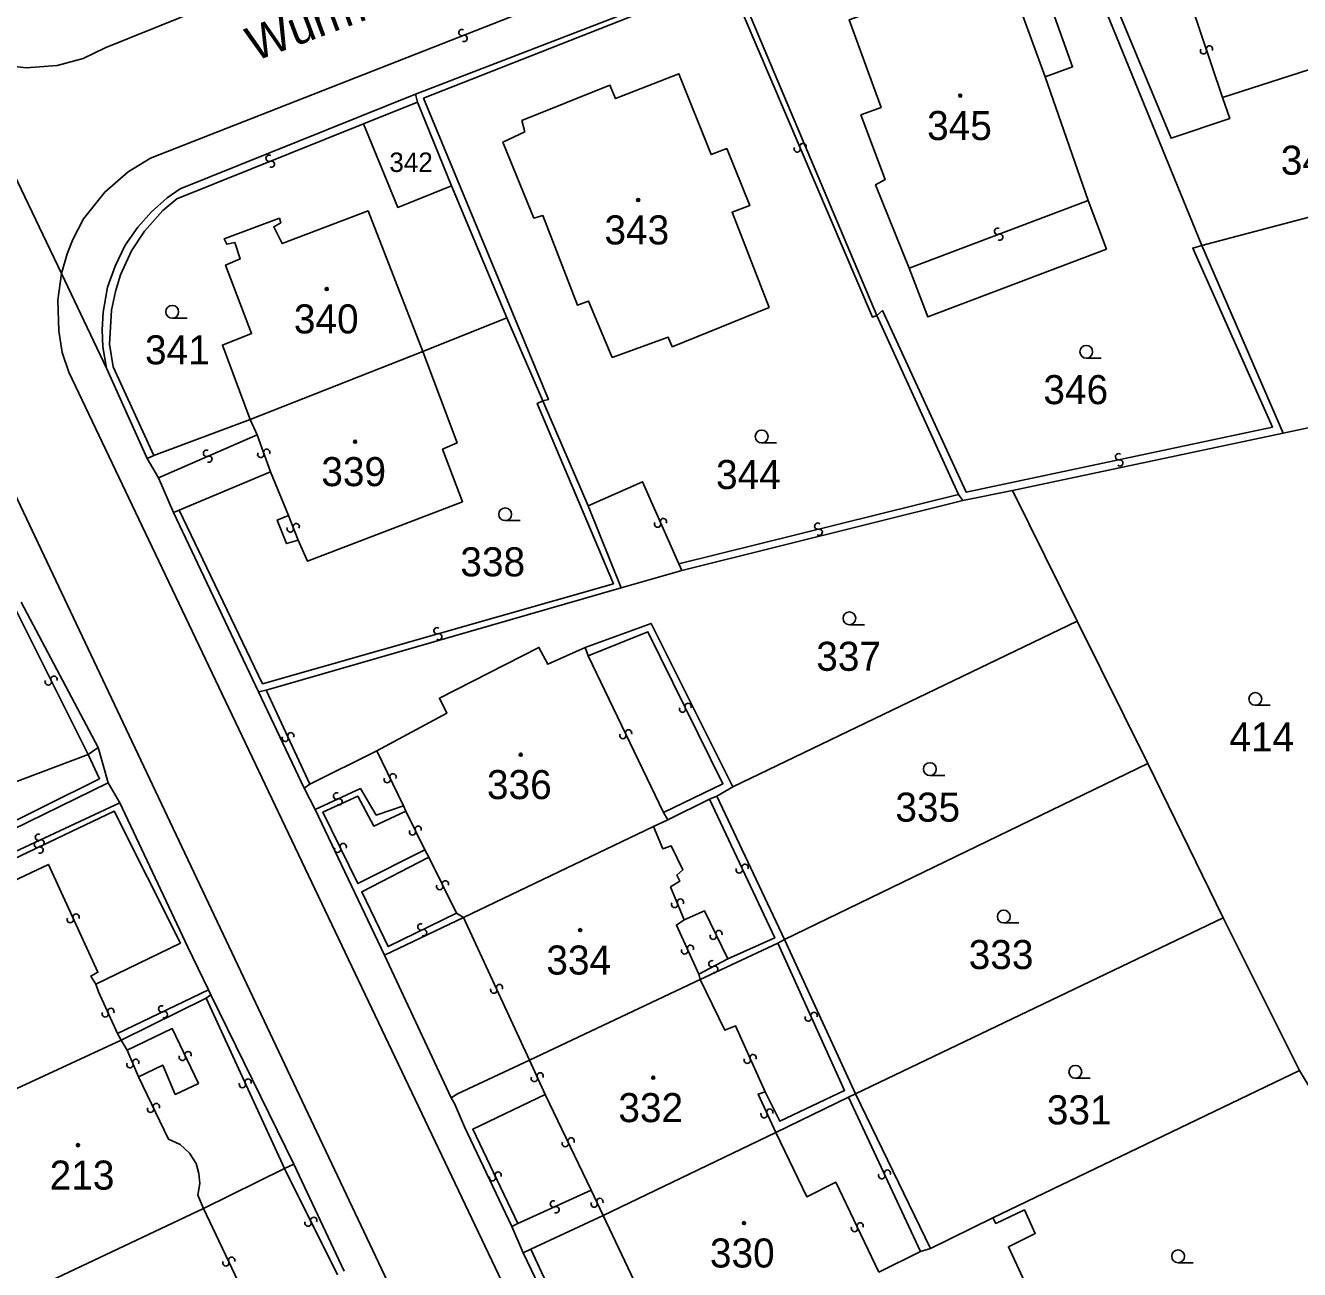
# Model space of a CAD drawing. Extents: x -600391 to -599491, y -1160176 to -1159402.
# Drawn here: x -600227.7 to -600153, y -1159733.9 to -1159661.1 of the extents above; entities that cross this region are included whole.
import ezdxf

# ---------------------------------------------------------------- set-up
doc = ezdxf.new("R2010")
doc.units = 0
for name, color, linetype in [('Level 1', 7, 'Continuous'), ('Level 11', 7, 'Continuous'), ('Level 13', 7, 'Continuous'), ('Level 3', 7, 'Continuous'), ('Level 4', 7, 'Continuous'), ('Level 5', 7, 'Continuous')]:
    doc.layers.add(name, color=color, linetype=linetype)

msp = doc.modelspace()

# ---------------------------------------------------------------- linework, layer by layer
at = {"layer": 'Level 1'}
for points in [[(-600170.28, -1159652.49), (-600166.33, -1159663.53), (-600167.93, -1159664.11)], [(-600160.77, -1159655.83), (-600164.91, -1159657.24), (-600160.56, -1159667.71), (-600157.13, -1159666.55), (-600157.55, -1159665.32)], [(-600165.9, -1159656.5), (-600158.77, -1159673.99)], [(-600204.82, -1159665.14), (-600186.4, -1159658.03)], [(-600175.9, -1159675.31), (-600177.87, -1159670.44), (-600177.31, -1159670.13), (-600178.73, -1159666.35), (-600177.55, -1159665.91), (-600179.41, -1159660.78), (-600170.34, -1159657.54)], [(-600186.15, -1159658.3), (-600177.79, -1159678.09)], [(-600157.55, -1159665.32), (-600151.9, -1159663.52), (-600152.17, -1159662.59), (-600147.93, -1159661.35)], [(-600231.91, -1159662.36), (-600226.43, -1159673.8), (-600225.55, -1159675.64)], [(-600184.1, -1159677.62), (-600189.78, -1159679.92), (-600190.02, -1159679.35), (-600193.29, -1159680.54), (-600194.68, -1159677.25), (-600195.33, -1159677.48), (-600197.36, -1159672.23), (-600197.89, -1159672.39), (-600199.7, -1159667.95), (-600198.41, -1159667.34), (-600198.58, -1159666.67), (-600193.43, -1159664.6), (-600193.09, -1159665.39), (-600189.39, -1159663.94), (-600187.5, -1159668.67), (-600186.58, -1159668.32), (-600185.24, -1159671.66), (-600186.27, -1159672.05), (-600184.1, -1159677.62)], [(-600167.93, -1159664.11), (-600165.41, -1159671.35)], [(-600204.82, -1159665.14), (-600218.6, -1159670.68), (-600219.35, -1159671.21), (-600220.28, -1159672.03), (-600221.08, -1159672.92), (-600221.81, -1159673.97), (-600222.41, -1159675.2), (-600222.85, -1159676.43), (-600223.1, -1159677.89), (-600223.16, -1159678.93), (-600223.12, -1159679.92), (-600222.9, -1159681.18)], [(-600207.85, -1159666.87), (-600204.69, -1159665.61)], [(-600204.82, -1159665.14), (-600204.69, -1159665.61)], [(-600204.69, -1159665.61), (-600202.7, -1159670.5)], [(-600202.7, -1159670.5), (-600205.85, -1159671.76), (-600207.85, -1159666.87)], [(-600202.7, -1159670.5), (-600199.46, -1159678.22)], [(-600144.73, -1159670.29), (-600158.77, -1159673.99)], [(-600165.41, -1159671.35), (-600164.35, -1159674.2), (-600174.81, -1159678.17), (-600175.9, -1159675.31)], [(-600214.49, -1159684.17), (-600216.12, -1159679.82), (-600214.41, -1159679.15), (-600215.93, -1159675.14), (-600215.08, -1159674.78), (-600215.4, -1159673.82), (-600215.87, -1159673.92), (-600216.01, -1159673.6), (-600212.78, -1159672.4), (-600212.69, -1159672.66), (-600213.11, -1159672.89), (-600212.62, -1159673.88), (-600207.59, -1159671.97), (-600204.38, -1159680.19)], [(-600158.77, -1159673.99), (-600153.99, -1159684.97)], [(-600222.9, -1159681.18), (-600225.55, -1159675.64)], [(-600116.25, -1159676.91), (-600153.99, -1159684.97)], [(-600204.38, -1159680.19), (-600199.46, -1159678.22)], [(-600199.46, -1159678.22), (-600197.36, -1159683.08)], [(-600177.79, -1159678.09), (-600173.02, -1159688.57)], [(-600214.49, -1159684.17), (-600204.38, -1159680.19)], [(-600211.68, -1159691.24), (-600211.14, -1159692.48), (-600202.06, -1159688.99), (-600203.23, -1159685.92), (-600202.38, -1159685.54), (-600204.38, -1159680.19)], [(-600220.52, -1159686.47), (-600222.9, -1159681.18)], [(-600197.36, -1159683.08), (-600194.7, -1159689.23)], [(-600220.13, -1159686.28), (-600214.49, -1159684.17)], [(-600153.99, -1159684.97), (-600169.84, -1159688.34)], [(-600220.52, -1159686.47), (-600220.13, -1159686.28)], [(-600219.87, -1159687.59), (-600220.52, -1159686.47)], [(-600218.65, -1159689.49), (-600213.3, -1159687.24)], [(-600213.3, -1159687.24), (-600212.25, -1159689.79)], [(-600218.99, -1159689.62), (-600219.87, -1159687.59)], [(-600173.02, -1159688.57), (-600172.76, -1159688.92)], [(-600172.76, -1159688.92), (-600169.84, -1159688.34)], [(-600169.84, -1159688.34), (-600166.06, -1159695.99)], [(-600218.99, -1159689.62), (-600218.65, -1159689.49)], [(-600194.7, -1159689.23), (-600192.77, -1159694.04)], [(-600189.22, -1159693.02), (-600172.76, -1159688.92)], [(-600214, -1159700.13), (-600218.99, -1159689.62)], [(-600212.25, -1159689.79), (-600212.91, -1159690.07), (-600212.36, -1159691.44), (-600211.68, -1159691.24)], [(-600192.77, -1159694.04), (-600189.22, -1159693.02)], [(-600213.56, -1159700.02), (-600192.77, -1159694.04)], [(-600223.39, -1159703.37), (-600227.91, -1159694.88)], [(-600194.87, -1159697.52), (-600191.02, -1159696.12), (-600186.23, -1159705.69)], [(-600186.23, -1159705.69), (-600166.06, -1159695.99)], [(-600166.06, -1159695.99), (-600161.93, -1159704.32)], [(-600207.07, -1159703.58), (-600202.98, -1159701.37), (-600203.41, -1159700.5), (-600197.58, -1159697.52), (-600197.06, -1159698.51), (-600194.87, -1159697.52)], [(-600214, -1159700.13), (-600213.56, -1159700.02)], [(-600211.33, -1159705.75), (-600214, -1159700.13)], [(-600223.99, -1159703.78), (-600223.39, -1159703.37)], [(-600222.82, -1159705.45), (-600223.39, -1159703.37)], [(-600211.01, -1159705.53), (-600207.07, -1159703.58)], [(-600244.9, -1159711.81), (-600241.06, -1159710.22), (-600223.99, -1159703.78)], [(-600183.2, -1159714.62), (-600161.93, -1159704.32)], [(-600161.93, -1159704.32), (-600157.51, -1159713.35)], [(-600222.13, -1159706.61), (-600222.82, -1159705.45)], [(-600211.33, -1159705.75), (-600211.01, -1159705.53)], [(-600210.69, -1159707), (-600211.33, -1159705.75)], [(-600187.16, -1159706.22), (-600186.23, -1159705.69)], [(-600216.94, -1159717.57), (-600218.15, -1159715.06), (-600222.13, -1159706.61)], [(-600190.03, -1159707.61), (-600187.59, -1159706.4)], [(-600187.59, -1159706.4), (-600187.16, -1159706.22)], [(-600187.16, -1159706.22), (-600183.2, -1159714.62)], [(-600206.62, -1159715.54), (-600210.69, -1159707)], [(-600202, -1159713.34), (-600190.88, -1159708.01)], [(-600190.88, -1159708.01), (-600190.03, -1159707.61)], [(-600206.62, -1159715.54), (-600202, -1159713.34)], [(-600179.05, -1159723.65), (-600157.51, -1159713.35)], [(-600157.51, -1159713.35), (-600153.05, -1159722.28)], [(-600188.15, -1159716.96), (-600183.6, -1159714.83)], [(-600183.6, -1159714.83), (-600183.2, -1159714.62)], [(-600183.2, -1159714.62), (-600179.05, -1159723.65)], [(-600202.72, -1159723.89), (-600206.62, -1159715.54)], [(-600198.13, -1159721.68), (-600188.15, -1159716.96)], [(-600217.08, -1159718.06), (-600216.79, -1159717.85)], [(-600216.79, -1159717.85), (-600216.94, -1159717.57)], [(-600211.94, -1159727.78), (-600216.79, -1159717.85)], [(-600222.05, -1159720.52), (-600217.08, -1159718.06)], [(-600232.68, -1159725.43), (-600222.05, -1159720.52)], [(-600202.72, -1159723.89), (-600202.36, -1159723.65), (-600198.13, -1159721.68)], [(-600171.01, -1159730.92), (-600153.05, -1159722.28)], [(-600153.05, -1159722.28), (-600152.3, -1159723.51)], [(-600179.45, -1159723.85), (-600179.05, -1159723.65)], [(-600179.05, -1159723.65), (-600174.65, -1159732.7)], [(-600199.18, -1159731.41), (-600201.95, -1159725.58), (-600202.52, -1159724.21), (-600202.72, -1159723.89)], [(-600183.7, -1159725.92), (-600179.45, -1159723.85)], [(-600193.83, -1159730.77), (-600183.7, -1159725.92)], [(-600217.22, -1159730.36), (-600212.49, -1159728.03)], [(-600212.49, -1159728.03), (-600211.94, -1159727.78)], [(-600208.99, -1159734.03), (-600211.94, -1159727.78)], [(-600227.96, -1159735.44), (-600217.22, -1159730.36)], [(-600171.01, -1159730.92), (-600170.82, -1159731.24), (-600169.15, -1159730.44), (-600168.52, -1159731.82), (-600170.09, -1159732.6), (-600166.61, -1159740.12), (-600171.26, -1159742.42)], [(-600198.05, -1159732.74), (-600193.83, -1159730.77)], [(-600174.65, -1159732.7), (-600171.01, -1159730.92)], [(-600198.5, -1159732.97), (-600199.18, -1159731.41)], [(-600198.5, -1159732.97), (-600198.05, -1159732.74)], [(-600175.23, -1159732.89), (-600174.65, -1159732.7)], [(-600195.05, -1159740.16), (-600198.5, -1159732.97)], [(-600177.67, -1159734.1), (-600175.23, -1159732.89)]]:
    msp.add_lwpolyline(points, dxfattribs=at)
at = {"layer": 'Level 13'}
for centre, start, end in [((-600202.096, -1159661.528), 58.58615, 291.17615), ((-600201.964, -1159661.872), 238.8006, 110.8986), ((-600158.665, -1159662.598), 145.87151, 18.46151), ((-600158.315, -1159662.482), 326.08596, 198.18396), ((-600182.46, -1159668.342), 150.31152, 22.90152), ((-600182.12, -1159668.199), 330.52598, 202.62397), ((-600213.387, -1159668.888), 59.23732, 291.33532), ((-600213.252, -1159669.231), 239.02287, 111.61287), ((-600170.724, -1159673.158), 57.83992, 290.42992), ((-600170.596, -1159673.503), 238.05438, 110.15237), ((-600217.052, -1159686.16), 60.92927, 293.02727), ((-600216.907, -1159686.499), 240.71481, 113.30481), ((-600213.874, -1159686.221), 147.37704, 19.47503), ((-600213.527, -1159686.098), 327.16258, 199.75258), ((-600163.637, -1159686.359), 49.36925, 281.46725), ((-600163.563, -1159686.72), 229.15479, 101.74479), ((-600190.629, -1159690.303), 150.84387, 23.43387), ((-600190.29, -1159690.157), 331.05833, 203.15632), ((-600181.253, -1159690.421), 51.29369, 283.39169), ((-600212.142, -1159690.586), 148.83269, 20.93069), ((-600211.798, -1159690.453), 328.61824, 201.20824), ((-600181.167, -1159690.779), 231.07924, 103.66924), ((-600203.549, -1159696.542), 53.28867, 285.38666), ((-600203.45, -1159696.897), 233.07421, 105.66421), ((-600225.984, -1159699.379), 333.91128, 206.00928), ((-600226.315, -1159699.542), 153.69683, 26.28683), ((-600189.175, -1159701.131), 153.41349, 26.00349), ((-600188.844, -1159700.97), 333.62794, 205.72594), ((-600212.448, -1159702.846), 152.20719, 24.30519), ((-600212.113, -1159702.693), 331.99274, 204.58274), ((-600192.666, -1159702.679), 152.86635, 25.45635), ((-600192.333, -1159702.522), 333.08081, 205.1788), ((-600206.134, -1159705.101), 332.9326, 205.5226), ((-600206.467, -1159705.259), 153.14705, 25.24505), ((-600209.436, -1159706.222), 62.09301, 294.191), ((-600209.284, -1159706.558), 241.87855, 114.46855), ((-600204.654, -1159708.16), 333.31626, 205.90626), ((-600226.958, -1159709.053), 62.54886, 295.13886), ((-600226.896, -1159708.632), 62.32947, 294.42747), ((-600226.743, -1159708.967), 242.11501, 114.70501), ((-600204.986, -1159708.32), 153.53072, 25.62871), ((-600226.802, -1159709.387), 242.76332, 114.86132), ((-600209.376, -1159709.34), 153.49748, 25.59548), ((-600209.044, -1159709.18), 333.28303, 205.87303), ((-600185.513, -1159710.392), 332.32545, 204.91545), ((-600185.848, -1159710.547), 152.53991, 24.63791), ((-600203.396, -1159711.52), 153.72714, 25.82514), ((-600203.065, -1159711.359), 333.51268, 206.10268), ((-600189.64, -1159712.57), 149.67266, 22.26266), ((-600189.299, -1159712.431), 329.88712, 201.98512), ((-600225.028, -1159713.456), 151.80681, 24.39681), ((-600224.692, -1159713.305), 332.02127, 204.11926), ((-600204.5, -1159713.884), 63.31984, 295.90984), ((-600204.34, -1159714.216), 243.5343, 115.6323), ((-600187.043, -1159714.271), 333.28394, 205.38194), ((-600187.376, -1159714.43), 153.06948, 25.65948), ((-600189.048, -1159715.285), 151.61722, 24.20722), ((-600188.711, -1159715.135), 331.83168, 203.92967), ((-600187.455, -1159716.037), 64.79166, 297.38166), ((-600187.286, -1159716.364), 245.00611, 117.10411), ((-600200.228, -1159717.586), 152.26539, 24.36339), ((-600199.893, -1159717.433), 332.05093, 204.64093), ((-600219.678, -1159718.683), 62.94031, 295.0383), ((-600222.988, -1159718.975), 151.42507, 24.01507), ((-600222.651, -1159718.826), 331.63952, 203.73752), ((-600219.521, -1159719.016), 242.72585, 115.31585), ((-600181.808, -1159719.215), 151.61225, 24.20225), ((-600181.471, -1159719.065), 331.8267, 203.9247), ((-600218.466, -1159721.518), 152.64241, 25.23241), ((-600218.133, -1159721.362), 332.85686, 204.95486), ((-600185.041, -1159721.536), 331.51401, 203.61201), ((-600221.53, -1159721.95), 149.77814, 22.36814), ((-600221.189, -1159721.811), 329.9926, 202.09059), ((-600185.378, -1159721.685), 151.29956, 23.88956), ((-600214.948, -1159723.116), 151.87873, 24.46873), ((-600214.612, -1159722.964), 332.09319, 204.19118), ((-600197.849, -1159722.755), 151.73072, 23.82872), ((-600197.512, -1159722.605), 331.51627, 204.10627), ((-600220.326, -1159724.559), 152.90126, 25.49126), ((-600219.993, -1159724.401), 333.11572, 205.21371), ((-600184.062, -1159724.724), 332.38963, 204.48763), ((-600184.397, -1159724.877), 152.17517, 24.76517), ((-600196.037, -1159726.569), 153.11344, 25.21144), ((-600195.704, -1159726.411), 332.89899, 205.48899), ((-600199.974, -1159728.411), 332.80266, 205.39266), ((-600177.172, -1159728.294), 332.39657, 204.49456), ((-600200.307, -1159728.568), 153.01711, 25.11511), ((-600177.507, -1159728.447), 152.18211, 24.77211), ((-600194.013, -1159729.953), 332.15398, 204.74398), ((-600196.735, -1159730.102), 61.92728, 294.02528), ((-600196.584, -1159730.438), 241.71282, 114.30282), ((-600194.348, -1159730.106), 152.36843, 24.46643), ((-600211.105, -1159731.222), 153.72333, 26.31333), ((-600210.774, -1159731.059), 333.93778, 206.03578), ((-600178.773, -1159731.382), 332.97492, 205.07292), ((-600179.106, -1159731.539), 152.76047, 25.35047), ((-600215.917, -1159733.548), 152.49256, 25.08256), ((-600215.583, -1159733.393), 332.70701, 204.80501)]:
    msp.add_arc(centre, 0.184, start, end, dxfattribs=at)
at = {"layer": 'Level 3'}
for points in [[(-600035.85, -1159643.34), (-600049.82, -1159635.36), (-600060.74, -1159631.3), (-600072.82, -1159629.21), (-600091.45, -1159629.86), (-600119.7, -1159635.07), (-600143.85, -1159641.26), (-600152.08, -1159643.56), (-600164.07, -1159647.45), (-600183.74, -1159654.52), (-600220.33, -1159668.88), (-600221.64, -1159669.68), (-600223.01, -1159670.87), (-600224.25, -1159672.44), (-600224.88, -1159673.64), (-600225.22, -1159674.49), (-600225.55, -1159675.64)], [(-600231.91, -1159662.36), (-600230.65, -1159662.97), (-600229.27, -1159663.39), (-600227.62, -1159663.59), (-600225.8, -1159663.45), (-600224.28, -1159663.04), (-600222.98, -1159662.43), (-600197.1, -1159651.98)], [(-600160.77, -1159655.83), (-600159.43, -1159659.77), (-600157.55, -1159665.32)], [(-600170.34, -1159657.54), (-600167.93, -1159664.11)], [(-600197.36, -1159683.08), (-600197.03, -1159683.01), (-600204.34, -1159665.37), (-600186.53, -1159658.35), (-600178.05, -1159678.18), (-600177.79, -1159678.09)], [(-600220.13, -1159686.28), (-600222.52, -1159681.09), (-600222.73, -1159679.77), (-600222.61, -1159677.77), (-600222.39, -1159676.68), (-600222.09, -1159675.71), (-600221.45, -1159674.31), (-600220.69, -1159673.15), (-600219.6, -1159671.95), (-600218.79, -1159671.26), (-600207.85, -1159666.87)], [(-600165.41, -1159671.35), (-600175.9, -1159675.31)], [(-600177.79, -1159678.09), (-600177.46, -1159677.8), (-600172.56, -1159688.44), (-600154.63, -1159684.63), (-600159.29, -1159674.14), (-600158.77, -1159673.99)], [(-600154.85, -1159824.6), (-600155.7, -1159824.37), (-600156.33, -1159824.07), (-600156.83, -1159823.72), (-600157.25, -1159823.34), (-600157.63, -1159822.87), (-600158.01, -1159822.25), (-600225.11, -1159681.41), (-600225.5, -1159680.26), (-600225.71, -1159678.98), (-600225.76, -1159677.2), (-600225.55, -1159675.64)], [(-600236.3, -1159676.88), (-600235.69, -1159677.1), (-600234.79, -1159677.54), (-600233.86, -1159678.21), (-600233.01, -1159679.1), (-600232.25, -1159680.16), (-600163.31, -1159825.79), (-600162.94, -1159826.86), (-600162.86, -1159827.88), (-600163.01, -1159828.81), (-600163.4, -1159829.75)], [(-600218.65, -1159689.49), (-600213.77, -1159699.65), (-600193.22, -1159693.79), (-600197.68, -1159683.24), (-600197.36, -1159683.08)], [(-600214.09, -1159685.07), (-600214.49, -1159684.17)], [(-600219.87, -1159687.59), (-600214.09, -1159685.07)], [(-600213.3, -1159687.24), (-600214.09, -1159685.07)], [(-600194.7, -1159689.23), (-600191.51, -1159687.82), (-600189.4, -1159692.63)], [(-600189.4, -1159692.63), (-600173.02, -1159688.57)], [(-600211.68, -1159691.24), (-600212.25, -1159689.79)], [(-600189.4, -1159692.63), (-600189.22, -1159693.02)], [(-600228.31, -1159695.13), (-600223.99, -1159703.78)], [(-600194.7, -1159698.02), (-600191.2, -1159696.6), (-600186.81, -1159705.5), (-600190.29, -1159707.18)], [(-600194.87, -1159697.52), (-600194.7, -1159698.02)], [(-600194.7, -1159698.02), (-600190.29, -1159707.18)], [(-600211.01, -1159705.53), (-600213.56, -1159700.02)], [(-600205.52, -1159706.79), (-600207.07, -1159703.58)], [(-600235.95, -1159711.87), (-600236.18, -1159711.6), (-600223.32, -1159705.21), (-600223.99, -1159703.78)], [(-600222.82, -1159705.45), (-600235.95, -1159711.87)], [(-600210.69, -1159707), (-600208.04, -1159705.78), (-600207.11, -1159707.34), (-600205.52, -1159706.79)], [(-600231.52, -1159710.98), (-600222.13, -1159706.61)], [(-600204.27, -1159709.37), (-600208.18, -1159711.35), (-600210.23, -1159707.17), (-600208.19, -1159706.22), (-600207.26, -1159707.98), (-600205.38, -1159707.11)], [(-600186.52, -1159715.76), (-600183.77, -1159714.53), (-600187.59, -1159706.4)], [(-600223.54, -1159717.24), (-600218.58, -1159714.83), (-600222.45, -1159707.11), (-600231.32, -1159711.32)], [(-600205.38, -1159707.11), (-600205.52, -1159706.79)], [(-600204.27, -1159709.37), (-600205.38, -1159707.11)], [(-600190.29, -1159707.18), (-600190.03, -1159707.61)], [(-600190.88, -1159708.01), (-600190.32, -1159709.31), (-600189.83, -1159709.14), (-600189.15, -1159710.54), (-600189.51, -1159710.85), (-600189.33, -1159711.2), (-600189.87, -1159711.54), (-600189.07, -1159713.47)], [(-600204.04, -1159709.8), (-600204.27, -1159709.37)], [(-600231.32, -1159711.32), (-600230.8, -1159712.34), (-600226.31, -1159710.22), (-600223.41, -1159716.54), (-600223.83, -1159716.76), (-600223.54, -1159717.24)], [(-600202.42, -1159713.07), (-600206.41, -1159715.03), (-600207.96, -1159711.82), (-600204.04, -1159709.8)], [(-600202.42, -1159713.07), (-600204.04, -1159709.8)], [(-600202, -1159713.34), (-600202.42, -1159713.07)], [(-600198.13, -1159721.68), (-600202, -1159713.34)], [(-600189.07, -1159713.47), (-600187.89, -1159712.94), (-600186.52, -1159715.76)], [(-600189.07, -1159713.47), (-600189.53, -1159713.77), (-600188.22, -1159716.65)], [(-600183.6, -1159714.83), (-600179.68, -1159723.45), (-600183.47, -1159725.26), (-600184.34, -1159723.54)], [(-600186.52, -1159715.76), (-600188.22, -1159716.65)], [(-600188.22, -1159716.65), (-600188.15, -1159716.96)], [(-600188.15, -1159716.96), (-600186.7, -1159719.93), (-600186.07, -1159719.68), (-600184.34, -1159723.54)], [(-600223.54, -1159717.24), (-600223.37, -1159717.68), (-600222.27, -1159720.12)], [(-600222.27, -1159720.12), (-600216.94, -1159717.57)], [(-600217.08, -1159718.06), (-600212.49, -1159728.03)], [(-600221.69, -1159721.1), (-600219.06, -1159719.83), (-600217.53, -1159723.04), (-600218.88, -1159723.69), (-600219.61, -1159721.97), (-600221.04, -1159722.66)], [(-600222.27, -1159720.12), (-600222.05, -1159720.52)], [(-600222.05, -1159720.52), (-600221.69, -1159721.1)], [(-600221.69, -1159721.1), (-600221.04, -1159722.66)], [(-600197.22, -1159723.69), (-600198.13, -1159721.68)], [(-600221.04, -1159722.66), (-600219.28, -1159726.31), (-600218.59, -1159726.62), (-600218.05, -1159727.12), (-600217.66, -1159727.74), (-600217.5, -1159728.31), (-600217.44, -1159728.9), (-600217.56, -1159729.58), (-600217.22, -1159730.36)], [(-600198.81, -1159731.25), (-600201.46, -1159725.73), (-600197.22, -1159723.69)], [(-600194.52, -1159729.29), (-600197.22, -1159723.69)], [(-600184.34, -1159723.54), (-600184.75, -1159723.67), (-600183.7, -1159725.92)], [(-600179.45, -1159723.85), (-600175.23, -1159732.89)], [(-600183.7, -1159725.92), (-600181.9, -1159729.68), (-600180.2, -1159728.82), (-600177.67, -1159734.1)], [(-600212.49, -1159728.03), (-600209.38, -1159734.25)], [(-600198.81, -1159731.25), (-600194.52, -1159729.29)], [(-600193.83, -1159730.77), (-600194.52, -1159729.29)], [(-600217.22, -1159730.36), (-600214.28, -1159736.57)], [(-600199.18, -1159731.41), (-600198.81, -1159731.25)], [(-600190.39, -1159738.01), (-600193.83, -1159730.77)], [(-600198.05, -1159732.74), (-600194.7, -1159739.97)]]:
    msp.add_lwpolyline(points, dxfattribs=at)
at = {"layer": 'Level 5'}
for p, q in [((-600219.06, -1159678.25), (-600218.185, -1159678.25)), ((-600165.53, -1159680.59), (-600164.655, -1159680.59)), ((-600184.54, -1159685.55), (-600183.665, -1159685.55)), ((-600199.56, -1159690.1), (-600198.685, -1159690.1)), ((-600179.4, -1159696.19), (-600178.525, -1159696.19)), ((-600155.63, -1159700.91), (-600154.755, -1159700.91)), ((-600174.69, -1159705.02), (-600173.815, -1159705.02)), ((-600170.36, -1159713.65), (-600169.485, -1159713.65)), ((-600166.17, -1159722.74), (-600165.295, -1159722.74)), ((-600160.15, -1159733.54), (-600159.275, -1159733.54))]:
    msp.add_line(p, q, dxfattribs=at)
for centre, radius in [((-600172.91, -1159665.22), 0.09), ((-600172.91, -1159665.22), 0.0521), ((-600191.77, -1159671.33), 0.09), ((-600191.77, -1159671.33), 0.0521), ((-600210.01, -1159676.54), 0.09), ((-600210.01, -1159676.54), 0.0521), ((-600219.06, -1159677.875), 0.375), ((-600165.53, -1159680.215), 0.375), ((-600184.54, -1159685.175), 0.375), ((-600208.35, -1159685.48), 0.09), ((-600208.35, -1159685.48), 0.0521), ((-600199.56, -1159689.725), 0.375), ((-600179.4, -1159695.815), 0.375), ((-600155.63, -1159700.535), 0.375), ((-600198.65, -1159703.8), 0.09), ((-600198.65, -1159703.8), 0.0521), ((-600174.69, -1159704.645), 0.375), ((-600170.36, -1159713.275), 0.375), ((-600195.17, -1159714.07), 0.09), ((-600195.17, -1159714.07), 0.0521), ((-600166.17, -1159722.365), 0.375), ((-600190.89, -1159722.71), 0.09), ((-600190.89, -1159722.71), 0.0521), ((-600224.58, -1159726.66), 0.09), ((-600224.58, -1159726.66), 0.0521), ((-600185.57, -1159731.22), 0.09), ((-600185.57, -1159731.22), 0.0521), ((-600160.15, -1159733.165), 0.375)]:
    msp.add_circle(centre, radius, dxfattribs=at)

# ---------------------------------------------------------------- texts
at = {"layer": 'Level 11'}
msp.add_text('Wurmova', height=2, rotation=20.48686, dxfattribs=at).set_placement((-600214.242, -1159663.232))
at = {"layer": 'Level 4'}
for s, height, p in [('345', 1.7, (-600174.852, -1159667.82)), ('342', 1.14, (-600206.344, -1159669.69)), ('347', 1.7, (-600154.136, -1159669.85)), ('343', 1.7, (-600193.748, -1159673.93)), ('340', 1.7, (-600211.935, -1159679.14)), ('341', 1.7, (-600220.654, -1159680.95)), ('346', 1.7, (-600168.041, -1159683.28)), ('339', 1.7, (-600210.328, -1159688.08)), ('344', 1.7, (-600187.211, -1159688.25)), ('338', 1.7, (-600202.186, -1159693.36)), ('337', 1.7, (-600181.342, -1159698.89)), ('414', 1.7, (-600157.147, -1159703.61)), ('336', 1.7, (-600200.628, -1159706.4)), ('335', 1.7, (-600176.709, -1159707.72)), ('333', 1.7, (-600172.415, -1159716.35)), ('334', 1.7, (-600197.148, -1159716.67)), ('332', 1.7, (-600192.933, -1159725.31)), ('331', 1.7, (-600167.841, -1159725.44)), ('213', 1.7, (-600226.239, -1159729.26)), ('330', 1.7, (-600187.571, -1159733.82))]:
    msp.add_text(s, height=height, dxfattribs=at).set_placement(p)

doc.saveas('drawing.dxf')
